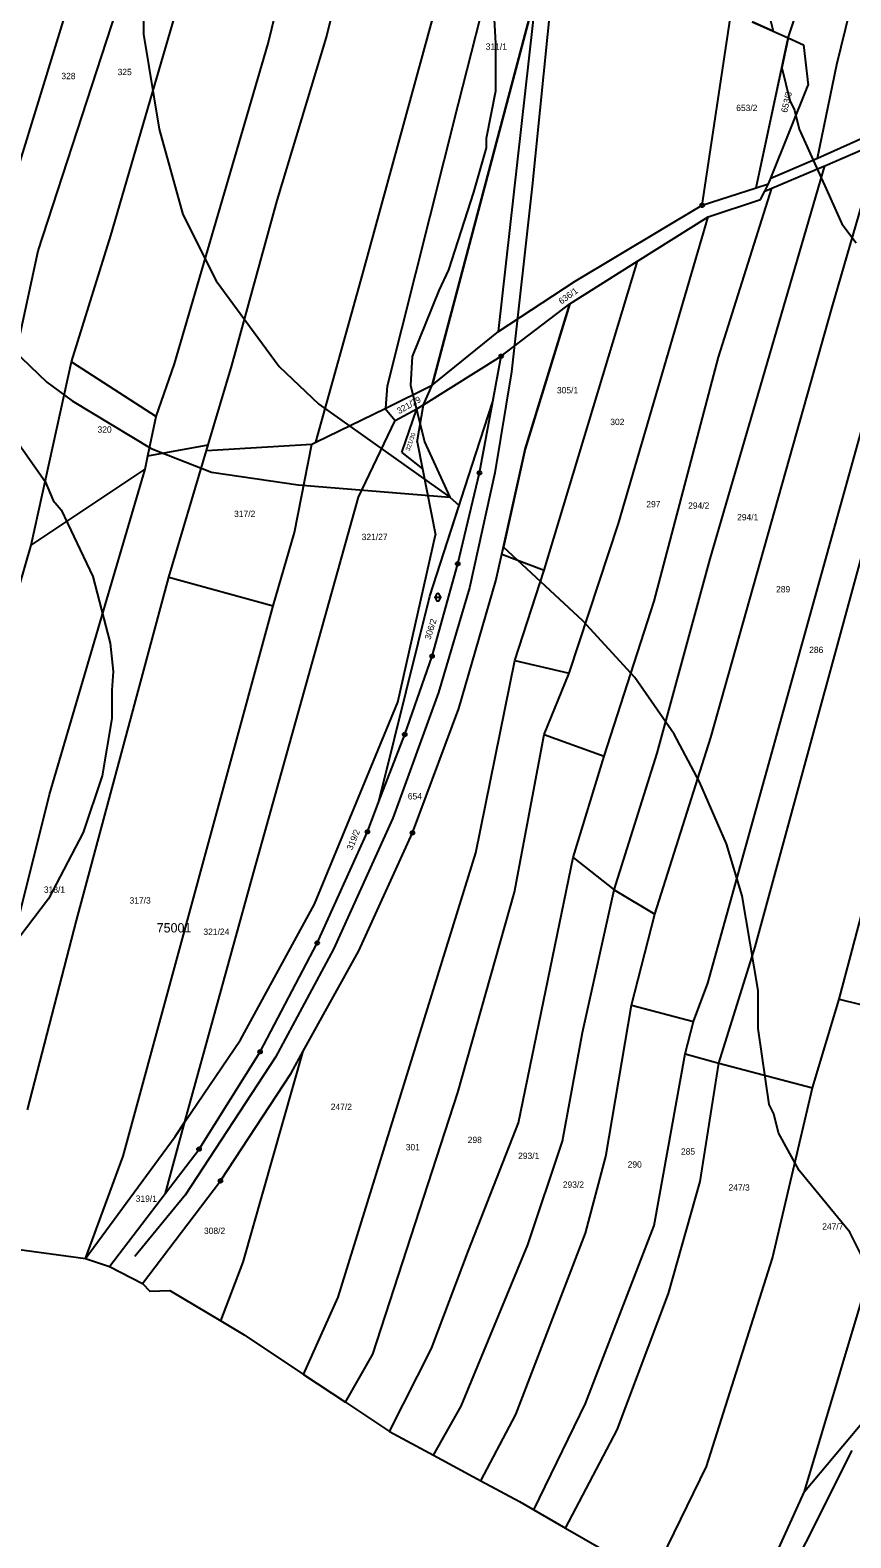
# Model space of a CAD drawing. Extents: x -743888 to -742027, y -1128394 to -1126768.
# Drawn here: x -743482 to -743261.6, y -1128081.8 to -1127677.1 of the extents above; entities that cross this region are included whole.
import ezdxf

# ---------------------------------------------------------------- set-up
doc = ezdxf.new("R2010")
doc.units = 0
for name, color, linetype in [('Vrstva 1', 7, 'Continuous'), ('Vrstva 10', 7, 'Continuous'), ('Vrstva 13', 7, 'Continuous'), ('Vrstva 18', 7, 'Continuous'), ('Vrstva 24', 7, 'Continuous'), ('Vrstva 25', 7, 'Continuous'), ('Vrstva 4', 7, 'Continuous'), ('Vrstva 52', 7, 'Continuous'), ('Vrstva 53', 7, 'Continuous'), ('Vrstva 6', 7, 'Continuous')]:
    doc.layers.add(name, color=color, linetype=linetype)

msp = doc.modelspace()

# ---------------------------------------------------------------- linework, layer by layer
at = {"layer": 'Vrstva 1'}
for points in [[(-743374.07, -1127772.46), (-743345.92, -1127666.2)], [(-743301.55, -1127724.14), (-743293.8, -1127672.4)], [(-743288.18, -1127674.9), (-743278.45, -1127679.23)], [(-743278.45, -1127679.23), (-743274.37, -1127681.04)], [(-743274.37, -1127681.04), (-743273.1, -1127691.93)], [(-743283.11, -1127716.84), (-743273.1, -1127691.93)], [(-743301.55, -1127724.14), (-743287.1, -1127719.44)], [(-743287.1, -1127719.44), (-743283.71, -1127718.34)], [(-743284.74, -1127720.35), (-743283.71, -1127718.34)], [(-743283.71, -1127718.34), (-743283.11, -1127716.84)], [(-743335.67, -1127744.51), (-743301.55, -1127724.14)], [(-743299.93, -1127727.23), (-743285.9, -1127722.61)], [(-743285.9, -1127722.61), (-743284.74, -1127720.35)], [(-743318.89, -1127739.14), (-743299.93, -1127727.23)], [(-743337.1, -1127750.58), (-743318.89, -1127739.14)], [(-743356.23, -1127757.98), (-743335.67, -1127744.51)], [(-743355.5, -1127764.66), (-743337.1, -1127750.58)], [(-743349.06, -1127789.63), (-743337.1, -1127750.58)], [(-743374.07, -1127772.46), (-743356.23, -1127757.98)], [(-743376.33, -1127777.73), (-743355.5, -1127764.66)], [(-743357.75, -1127776.76), (-743355.5, -1127764.66)], [(-743376.33, -1127777.73), (-743374.07, -1127772.46)], [(-743361.33, -1127795.97), (-743357.75, -1127776.76)], [(-743378.06, -1127787.61), (-743376.33, -1127777.73)], [(-743378.06, -1127787.61), (-743376.61, -1127794.9)], [(-743355.31, -1127817.79), (-743349.06, -1127789.63)], [(-743376.61, -1127794.9), (-743373.1, -1127812.6)], [(-743367.18, -1127820.36), (-743361.33, -1127795.97)], [(-743383.25, -1127857.46), (-743373.1, -1127812.6)], [(-743374.06, -1127845.14), (-743367.18, -1127820.36)], [(-743356.91, -1127824.97), (-743355.31, -1127817.79)], [(-743366.89, -1127859.22), (-743356.91, -1127824.97)], [(-743381.41, -1127866.19), (-743374.06, -1127845.14)], [(-743405.64, -1127911.7), (-743383.25, -1127857.46)], [(-743379.33, -1127892.58), (-743366.89, -1127859.22)], [(-743388.31, -1127884.17), (-743381.41, -1127866.19)], [(-743391.42, -1127892.28), (-743388.31, -1127884.17)], [(-743404.89, -1127922.15), (-743391.42, -1127892.28)], [(-743393.74, -1127924.28), (-743379.33, -1127892.58)], [(-743425.47, -1127948.11), (-743405.64, -1127911.7)], [(-743420.24, -1127951.33), (-743404.89, -1127922.15)], [(-743408.65, -1127951.21), (-743393.74, -1127924.28)], [(-743440.39, -1127970.17), (-743425.47, -1127948.11)], [(-743436.62, -1127977.47), (-743420.24, -1127951.33)], [(-743411.91, -1127957.1), (-743408.65, -1127951.21)], [(-743430.86, -1127985.98), (-743411.91, -1127957.1)], [(-743443.01, -1127974.04), (-743440.39, -1127970.17)], [(-743467.06, -1128006.86), (-743443.01, -1127974.04)], [(-743445.65, -1127989.32), (-743436.62, -1127977.47)], [(-743451.84, -1128013.54), (-743430.86, -1127985.98)], [(-743460.67, -1128009.01), (-743445.65, -1127989.32)]]:
    msp.add_lwpolyline(points, dxfattribs=at)
at = {"layer": 'Vrstva 10'}
for p, q in [((-743352.72, -1127768.88), (-743357.17, -1127795.95)), ((-743357.17, -1127795.95), (-743364.05, -1127826.81)), ((-743364.05, -1127826.81), (-743372.31, -1127854.95)), ((-743372.31, -1127854.95), (-743384.6, -1127888.63)), ((-743384.6, -1127888.63), (-743400.5, -1127923.77)), ((-743400.5, -1127923.77), (-743416.09, -1127952.75)), ((-743416.09, -1127952.75), (-743440.32, -1127989.82)), ((-743440.32, -1127989.82), (-743453.83, -1128006.28))]:
    msp.add_line(p, q, dxfattribs=at)
for points in [[(-743338.02, -1127627.59), (-743347.15, -1127719.04)], [(-743347.15, -1127719.04), (-743352.72, -1127768.88)]]:
    msp.add_lwpolyline(points, dxfattribs=at)
at = {"layer": 'Vrstva 13'}
for points in [[(-743494.24, -1128003.18), (-743467.06, -1128006.86)], [(-743467.06, -1128006.86), (-743460.67, -1128009.01)], [(-743460.67, -1128009.01), (-743451.84, -1128013.54)], [(-743451.84, -1128013.54), (-743449.85, -1128015.59)], [(-743449.85, -1128015.59), (-743444.44, -1128015.41)], [(-743444.44, -1128015.41), (-743430.75, -1128023.58)], [(-743430.75, -1128023.58), (-743424.49, -1128027.31)], [(-743424.49, -1128027.31), (-743408.55, -1128037.93)], [(-743408.55, -1128037.93), (-743397.3, -1128045.42)], [(-743397.3, -1128045.42), (-743385.5, -1128053.28)], [(-743385.5, -1128053.28), (-743373.72, -1128059.62)], [(-743373.72, -1128059.62), (-743360.94, -1128066.49)], [(-743360.94, -1128066.49), (-743350.56, -1128072.08)], [(-743350.56, -1128072.08), (-743346.77, -1128074.27)], [(-743346.77, -1128074.27), (-743338.22, -1128079.2)], [(-743338.22, -1128079.2), (-743323.15, -1128087.88)]]:
    msp.add_lwpolyline(points, dxfattribs=at)
at = {"layer": 'Vrstva 24'}
for p, q in [((-743301.6, -1127724.14), (-743301.5, -1127724.14)), ((-743355.55, -1127764.66), (-743355.45, -1127764.66)), ((-743361.38, -1127795.97), (-743361.28, -1127795.97)), ((-743367.23, -1127820.36), (-743367.13, -1127820.36)), ((-743374.11, -1127845.14), (-743374.01, -1127845.14)), ((-743381.46, -1127866.19), (-743381.36, -1127866.19)), ((-743391.47, -1127892.28), (-743391.37, -1127892.28)), ((-743379.38, -1127892.58), (-743379.28, -1127892.58)), ((-743404.94, -1127922.15), (-743404.84, -1127922.15)), ((-743420.29, -1127951.33), (-743420.19, -1127951.33)), ((-743436.67, -1127977.47), (-743436.57, -1127977.47)), ((-743430.91, -1127985.98), (-743430.81, -1127985.98))]:
    msp.add_line(p, q, dxfattribs=at)
for centre in [(-743301.55, -1127724.14), (-743355.5, -1127764.66), (-743361.33, -1127795.97), (-743367.18, -1127820.36), (-743374.06, -1127845.14), (-743381.41, -1127866.19), (-743391.42, -1127892.28), (-743379.33, -1127892.58), (-743404.89, -1127922.15), (-743420.24, -1127951.33), (-743436.62, -1127977.47), (-743430.86, -1127985.98)]:
    msp.add_circle(centre, 0.499, dxfattribs=at)
at = {"layer": 'Vrstva 25'}
for p, q in [((-743373.51, -1127829.35), (-743371.51, -1127829.35)), ((-743373.01, -1127828.85), (-743373.01, -1127829.85)), ((-743372.01, -1127828.85), (-743372.01, -1127829.85))]:
    msp.add_line(p, q, dxfattribs=at)
for centre, start, end in [((-743372.51, -1127828.85), 0, 180), ((-743372.51, -1127829.85), 180, 0)]:
    msp.add_arc(centre, 0.5, start, end, dxfattribs=at)
at = {"layer": 'Vrstva 4'}
msp.add_lwpolyline([(-743356.23, -1127757.98), (-743345.92, -1127666.2)], dxfattribs=at)
at = {"layer": 'Vrstva 52'}
for points in [[(-743053.67, -1127722.32), (-743058.31, -1127718.5), (-743079.93, -1127701.11), (-743080.38, -1127700.75), (-743105, -1127679.13), (-743127.88, -1127660), (-743130, -1127657.5), (-743148.25, -1127642.13), (-743183.06, -1127617.63), (-743185.22, -1127616.53), (-743196.63, -1127610.75), (-743212.31, -1127605.25), (-743222.5, -1127604.38), (-743235.19, -1127605.75), (-743244.13, -1127607.38), (-743252.19, -1127610.75), (-743260.69, -1127617.13), (-743270.44, -1127627.38), (-743275.94, -1127635), (-743280.63, -1127645.13), (-743281.88, -1127655.38), (-743283.19, -1127657.88), (-743283.56, -1127673.13), (-743282.53, -1127677.41)], [(-743358.25, -1127657.88), (-743357, -1127680.75), (-743357, -1127693.5), (-743359.5, -1127706.25), (-743359.5, -1127708.75), (-743362.94, -1127720.63), (-743369.69, -1127741.5), (-743372.25, -1127747), (-743379.44, -1127764.75), (-743379.88, -1127772.38), (-743376.06, -1127787.63), (-743369.25, -1127802.5)], [(-743345.92, -1127666.2), (-743374.07, -1127772.46), (-743356.23, -1127757.98), (-743335.67, -1127744.51), (-743301.55, -1127724.14), (-743287.1, -1127719.44), (-743280.17, -1127687.23)], [(-743451.56, -1127673.13), (-743451.56, -1127678.25), (-743447.31, -1127703.75), (-743441, -1127726.63), (-743432.06, -1127744.38), (-743415.13, -1127767.38), (-743404.5, -1127777.5), (-743369.25, -1127802.5)], [(-743282.53, -1127677.41), (-743288.18, -1127674.9)], [(-743282.53, -1127677.41), (-743278.45, -1127679.23), (-743280.17, -1127687.23)], [(-743280.17, -1127687.23), (-743278.06, -1127696), (-743276.81, -1127698.63), (-743275.5, -1127703.75), (-743267.44, -1127721.5), (-743264.06, -1127729.13), (-743260.25, -1127734.25)], [(-743545.75, -1127716), (-743540.25, -1127718.5), (-743503.31, -1127746.13), (-743493.56, -1127756.25), (-743477.44, -1127771.63), (-743470.69, -1127776.63), (-743449.44, -1127789.38), (-743433.31, -1127795.75), (-743410, -1127799.13), (-743369.25, -1127802.5)], [(-743366.83, -1127804.75), (-743366.25, -1127802.98), (-743362.23, -1127790.56), (-743357.75, -1127776.76), (-743355.5, -1127764.66), (-743337.1, -1127750.58), (-743349.06, -1127789.63), (-743354.88, -1127815.86)], [(-743486.81, -1127785.63), (-743477.88, -1127798.25), (-743475.75, -1127803.38), (-743473.63, -1127805.88), (-743465.13, -1127823.75), (-743460.5, -1127841.63), (-743459.63, -1127849.25), (-743460.06, -1127854.25), (-743460.06, -1127861.88), (-743462.63, -1127877.25), (-743467.69, -1127892.5), (-743477.06, -1127910.25), (-743490.63, -1127928.13)], [(-743460.67, -1128009.01), (-743445.65, -1127989.32), (-743436.62, -1127977.47), (-743420.24, -1127951.33), (-743404.89, -1127922.15), (-743391.42, -1127892.28), (-743388.31, -1127884.17), (-743384.13, -1127867.26), (-743374.7, -1127829.05), (-743366.83, -1127804.75)], [(-743369.25, -1127802.5), (-743366.83, -1127804.75)], [(-743451.84, -1128013.54), (-743430.86, -1127985.98), (-743411.91, -1127957.1), (-743408.65, -1127951.21), (-743393.74, -1127924.28), (-743379.33, -1127892.58), (-743366.89, -1127859.22), (-743356.91, -1127824.97), (-743355.31, -1127817.79), (-743354.88, -1127815.86)], [(-743251.75, -1128020.13), (-743261.94, -1127999.75), (-743275.5, -1127983.25), (-743281.06, -1127973.13), (-743282.31, -1127968), (-743283.56, -1127965.5), (-743286.56, -1127945.13), (-743286.56, -1127934.88), (-743290.81, -1127909.5), (-743295.06, -1127895.5), (-743302.25, -1127878.88), (-743309.06, -1127866.13), (-743319.63, -1127850.88), (-743333.63, -1127835.63), (-743354.88, -1127815.86)], [(-743494.24, -1128003.18), (-743467.06, -1128006.86), (-743460.67, -1128009.01)], [(-743451.84, -1128013.54), (-743449.85, -1128015.59), (-743444.44, -1128015.41), (-743430.75, -1128023.58), (-743424.49, -1128027.31), (-743408.55, -1128037.93), (-743397.3, -1128045.42), (-743385.5, -1128053.28), (-743373.72, -1128059.62), (-743360.94, -1128066.49), (-743350.56, -1128072.08), (-743346.77, -1128074.27), (-743338.22, -1128079.2), (-743323.15, -1128087.88)]]:
    msp.add_lwpolyline(points, dxfattribs=at)
at = {"layer": 'Vrstva 6'}
for points in [[(-743402.41, -1127679.01), (-743378.99, -1127584.19)], [(-743265.43, -1127686.37), (-743248.78, -1127618.41)], [(-743392.64, -1127742.44), (-743360.58, -1127625.49)], [(-743418.02, -1127680.71), (-743407.6, -1127637.74)], [(-743460.31, -1127732.22), (-743435.59, -1127647.51)], [(-743366.95, -1127696.84), (-743357.58, -1127659.83)], [(-743494.95, -1127745.55), (-743469.86, -1127664.22)], [(-743479.83, -1127736.34), (-743456.19, -1127663.78)], [(-743278.45, -1127679.23), (-743274.02, -1127665.56)], [(-743415.63, -1127722.89), (-743402.41, -1127679.01)], [(-743287.1, -1127719.44), (-743278.45, -1127679.23)], [(-743443.18, -1127766.73), (-743418.02, -1127680.71)], [(-743270.64, -1127711.51), (-743265.43, -1127686.37)], [(-743386.06, -1127772.64), (-743366.95, -1127696.84)], [(-743270.64, -1127711.51), (-743255.66, -1127704.74)], [(-743268.66, -1127713.55), (-743253.81, -1127707.15)], [(-743266.62, -1127751.47), (-743253.81, -1127707.15)], [(-743283.11, -1127716.84), (-743270.64, -1127711.51)], [(-743299.42, -1127819.01), (-743268.66, -1127713.55)], [(-743282.88, -1127719.56), (-743268.87, -1127713.64)], [(-743268.87, -1127713.64), (-743268.66, -1127713.55)], [(-743297.14, -1127764.91), (-743282.88, -1127719.56)], [(-743284.74, -1127720.35), (-743282.88, -1127719.56)], [(-743427.78, -1127767.16), (-743415.63, -1127722.89)], [(-743324.05, -1127809.53), (-743299.93, -1127727.23)], [(-743470.88, -1127766.12), (-743460.31, -1127732.22)], [(-743486.56, -1127767.82), (-743479.83, -1127736.34)], [(-743343.93, -1127822.1), (-743318.89, -1127739.14)], [(-743405.3, -1127787.74), (-743392.64, -1127742.44)], [(-743300.05, -1127932.95), (-743249, -1127749.54)], [(-743299.27, -1127867.01), (-743266.62, -1127751.47)], [(-743481.69, -1127815.4), (-743470.88, -1127766.12)], [(-743470.88, -1127766.12), (-743448.1, -1127780.84)], [(-743448.1, -1127780.84), (-743443.18, -1127766.73)], [(-743434.17, -1127788.45), (-743427.78, -1127767.16)], [(-743314.44, -1127830.42), (-743297.14, -1127764.91)], [(-743386.45, -1127778.59), (-743374.07, -1127772.46)], [(-743386.45, -1127778.59), (-743386.06, -1127772.64)], [(-743362.23, -1127790.56), (-743357.75, -1127776.76)], [(-743450.34, -1127791.41), (-743448.1, -1127780.84)], [(-743405.3, -1127787.74), (-743386.64, -1127778.68)], [(-743386.64, -1127778.68), (-743386.45, -1127778.59)], [(-743386.64, -1127778.68), (-743383.94, -1127781.89)], [(-743383.94, -1127781.89), (-743378.18, -1127778.74)], [(-743382.22, -1127790.53), (-743378.18, -1127778.74)], [(-743378.18, -1127778.74), (-743376.33, -1127777.73)], [(-743393.77, -1127802.48), (-743383.94, -1127781.89)], [(-743450.34, -1127791.41), (-743434.17, -1127788.45)], [(-743434.62, -1127789.95), (-743406.34, -1127788.25)], [(-743434.62, -1127789.95), (-743434.17, -1127788.45)], [(-743411.02, -1127811.93), (-743406.34, -1127788.25)], [(-743406.34, -1127788.25), (-743405.3, -1127787.74)], [(-743287.33, -1127923.2), (-743249.75, -1127785.46)], [(-743451.09, -1127794.94), (-743450.34, -1127791.41)], [(-743444.74, -1127823.92), (-743434.62, -1127789.95)], [(-743382.22, -1127790.53), (-743376.61, -1127794.9)], [(-743366.25, -1127802.98), (-743362.23, -1127790.56)], [(-743481.69, -1127815.4), (-743451.09, -1127794.94)], [(-743476.79, -1127882.29), (-743451.09, -1127794.94)], [(-743422.4, -1127904.63), (-743393.77, -1127802.48)], [(-743374.7, -1127829.05), (-743366.25, -1127802.98)], [(-743416.75, -1127831.61), (-743411.02, -1127811.93)], [(-743337.26, -1127849.72), (-743324.05, -1127809.53)], [(-743490.01, -1127844.27), (-743481.69, -1127815.4)], [(-743355.31, -1127817.79), (-743343.93, -1127822.1)], [(-743313.64, -1127871.22), (-743299.42, -1127819.01)], [(-743469.54, -1127916.07), (-743444.74, -1127823.92)], [(-743444.74, -1127823.92), (-743416.75, -1127831.61)], [(-743351.87, -1127846.33), (-743343.93, -1127822.1)], [(-743384.13, -1127867.26), (-743374.7, -1127829.05)], [(-743456.95, -1127979.38), (-743416.75, -1127831.61)], [(-743327.83, -1127872.04), (-743314.44, -1127830.42)], [(-743362.28, -1127897.95), (-743351.87, -1127846.33)], [(-743351.87, -1127846.33), (-743337.26, -1127849.72)], [(-743344, -1127866.17), (-743337.26, -1127849.72)], [(-743264.74, -1127937.21), (-743244.37, -1127860.25)], [(-743388.31, -1127884.17), (-743384.13, -1127867.26)], [(-743351.96, -1127908.52), (-743344, -1127866.17)], [(-743344, -1127866.17), (-743327.83, -1127872.04)], [(-743314.24, -1127914.43), (-743299.27, -1127867.01)], [(-743336.15, -1127899.16), (-743327.83, -1127872.04)], [(-743325.19, -1127907.9), (-743313.64, -1127871.22)], [(-743506.61, -1128001.51), (-743476.79, -1127882.29)], [(-743399.31, -1128017.21), (-743362.28, -1127897.95)], [(-743350.84, -1127970.39), (-743336.15, -1127899.16)], [(-743336.15, -1127899.16), (-743325.19, -1127907.9)], [(-743440.39, -1127970.17), (-743422.4, -1127904.63)], [(-743367.18, -1127962.23), (-743351.96, -1127908.52)], [(-743333.67, -1127946.14), (-743325.19, -1127907.9)], [(-743325.19, -1127907.9), (-743314.24, -1127914.43)], [(-743482.7, -1127966.88), (-743469.54, -1127916.07)], [(-743320.49, -1127938.82), (-743314.24, -1127914.43)], [(-743297.04, -1127954.42), (-743287.33, -1127923.2)], [(-743303.92, -1127943.26), (-743300.05, -1127932.95)], [(-743271.96, -1127961.06), (-743264.74, -1127937.21)], [(-743264.74, -1127937.21), (-743237.87, -1127943.87)], [(-743327.4, -1127979.41), (-743320.49, -1127938.82)], [(-743320.49, -1127938.82), (-743303.92, -1127943.26)], [(-743339.02, -1127975.31), (-743333.67, -1127946.14)], [(-743306.09, -1127951.87), (-743303.92, -1127943.26)], [(-743424.74, -1128007.83), (-743408.65, -1127951.21)], [(-743314.44, -1127998.01), (-743306.09, -1127951.87)], [(-743306.09, -1127951.87), (-743297.04, -1127954.42)], [(-743302.13, -1127986.13), (-743297.04, -1127954.42)], [(-743297.04, -1127954.42), (-743271.96, -1127961.06)], [(-743390, -1128032.51), (-743367.18, -1127962.23)], [(-743282.67, -1128006.78), (-743271.96, -1127961.06)], [(-743445.65, -1127989.32), (-743440.39, -1127970.17)], [(-743364.27, -1128004.65), (-743350.84, -1127970.39)], [(-743348.37, -1128003.17), (-743339.02, -1127975.31)], [(-743467.06, -1128006.86), (-743456.95, -1127979.38)], [(-743332.84, -1128000.03), (-743327.4, -1127979.41)], [(-743310.6, -1128016.21), (-743302.13, -1127986.13)], [(-743332.92, -1128045.71), (-743314.44, -1127998.01)], [(-743366.24, -1128046.5), (-743348.37, -1128003.17)], [(-743351.58, -1128048.72), (-743332.84, -1128000.03)], [(-743374.19, -1128031.01), (-743364.27, -1128004.65)], [(-743300.41, -1128062.62), (-743282.67, -1128006.78)], [(-743274.12, -1128069.36), (-743254.82, -1128005.17)], [(-743430.75, -1128023.58), (-743424.74, -1128007.83)], [(-743408.55, -1128037.93), (-743399.31, -1128017.21)], [(-743324.39, -1128052.82), (-743310.6, -1128016.21)], [(-743274.12, -1128069.36), (-743232.97, -1128020.31)], [(-743385.5, -1128053.28), (-743374.19, -1128031.01)], [(-743397.3, -1128045.42), (-743390, -1128032.51)], [(-743373.72, -1128059.62), (-743366.24, -1128046.5)], [(-743346.77, -1128074.27), (-743332.92, -1128045.71)], [(-743360.94, -1128066.49), (-743351.58, -1128048.72)], [(-743338.22, -1128079.2), (-743324.39, -1128052.82)], [(-743286.03, -1128107.53), (-743261.3, -1128058.36)], [(-743315.96, -1128094.6), (-743300.41, -1128062.62)], [(-743294.54, -1128114.63), (-743274.12, -1128069.36)]]:
    msp.add_lwpolyline(points, dxfattribs=at)

# ---------------------------------------------------------------- texts
at = {"layer": 'Vrstva 18'}
for s, p in [('311/1', (-743359.65, -1127682.4)), ('325', (-743458.48, -1127689.21)), ('328', (-743473.57, -1127690.29)), ('653/2', (-743292.41, -1127698.85)), ('305/1', (-743340.54, -1127774.63)), ('320', (-743463.87, -1127785.17)), ('302', (-743326.22, -1127783.14)), ('297', (-743316.55, -1127805.21)), ('294/2', (-743305.33, -1127805.6)), ('317/2', (-743427.21, -1127807.81)), ('294/1', (-743292.17, -1127808.7)), ('321/27', (-743392.96, -1127814.01)), ('289', (-743281.72, -1127828.05)), ('286', (-743272.83, -1127844.32)), ('654', (-743380.57, -1127883.62)), ('318/1', (-743478.27, -1127908.68)), ('317/3', (-743455.28, -1127911.56)), ('321/24', (-743435.44, -1127919.97)), ('247/2', (-743401.25, -1127966.95)), ('298', (-743364.5, -1127975.85)), ('301', (-743381.13, -1127977.79)), ('293/1', (-743350.96, -1127980.11)), ('285', (-743307.25, -1127978.95)), ('290', (-743321.56, -1127982.43)), ('293/2', (-743338.97, -1127987.85)), ('247/3', (-743294.48, -1127988.62)), ('319/1', (-743453.61, -1127991.62)), ('308/2', (-743435.29, -1128000.24)), ('247/7', (-743269.33, -1127999.08))]:
    msp.add_text(s, height=1.7, dxfattribs=at).set_placement(p)
for s, height, rotation, p in [('653/3', 1.7, 76.4514, (-743278.77, -1127699.41)), ('636/1', 1.7, 35.8418, (-743339.33, -1127750.81)), ('321/29', 1.7, 29.7121, (-743382.9, -1127780.22)), ('321/30', 1.19, 70.7273, (-743380.11, -1127790.16)), ('306/2', 1.7, 72.3942, (-743374.52, -1127840.88)), ('319/2', 1.7, 67.6836, (-743395.51, -1127897.37))]:
    msp.add_text(s, height=height, rotation=rotation, dxfattribs=at).set_placement(p)
at = {"layer": 'Vrstva 53'}
msp.add_text('75001', height=2.5, dxfattribs=at).set_placement((-743447.98, -1127919.32))

doc.saveas('drawing.dxf')
